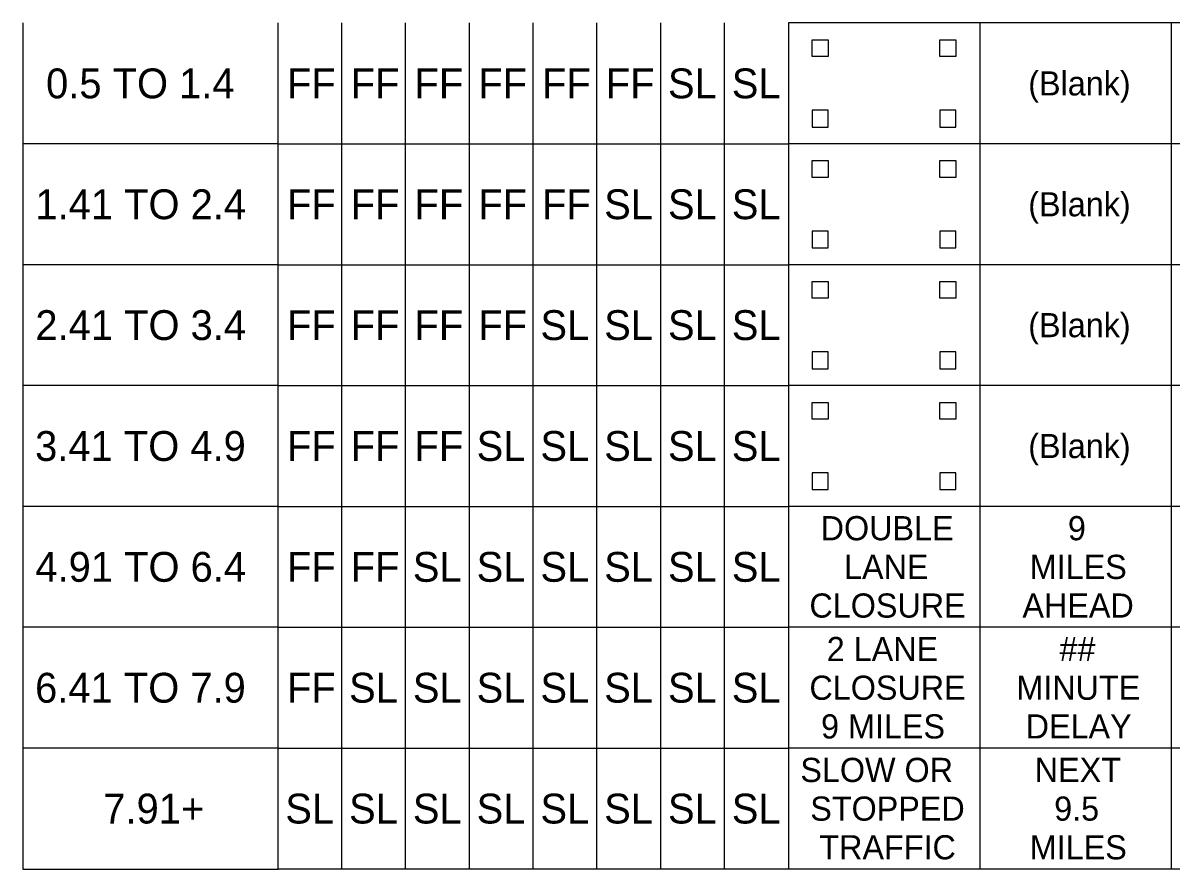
# Model space of a CAD drawing. Extents: x 99999.1 to 100055.7, y 99995 to 100017.5.
# Drawn here: x 100024.329 to 100027.417, y 100001.966 to 100004.241 of the extents above; entities that cross this region are included whole.
import ezdxf

# ---------------------------------------------------------------- set-up
doc = ezdxf.new("R2010")
doc.units = 0
doc.layers.add('TR_WZ_WorkZoneDetails', color=7, linetype='Continuous')
doc.layers.add('TR_WZ_WorkZoneTextCurrent', color=7, linetype='Continuous')

msp = doc.modelspace()

# ---------------------------------------------------------------- linework, layer by layer
at = {"layer": 'TR_WZ_WorkZoneDetails'}
for p, q in [((100024.3292, 100004.2408), (100024.3292, 100003.9158)), ((100025.0153, 100003.9158), (100025.0153, 100004.2408)), ((100025.1868, 100003.9158), (100025.1868, 100004.2408)), ((100025.1868, 100003.9158), (100025.1868, 100004.2408)), ((100025.3583, 100003.9158), (100025.3583, 100004.2408)), ((100025.3583, 100003.9158), (100025.3583, 100004.2408)), ((100025.5299, 100003.9158), (100025.5299, 100004.2408)), ((100025.7014, 100003.9158), (100025.7014, 100004.2408)), ((100025.8729, 100003.9158), (100025.8729, 100004.2408)), ((100026.0444, 100003.9158), (100026.0444, 100004.2408)), ((100026.216, 100003.9158), (100026.216, 100004.2408)), ((100026.3875, 100004.2408), (100026.3875, 100003.9158)), ((100027.4167, 100004.2408), (100026.3875, 100004.2408)), ((100026.9021, 100004.2408), (100026.9021, 100003.9158)), ((100028.4458, 100004.2408), (100027.4167, 100004.2408)), ((100027.4167, 100004.2408), (100027.4167, 100003.9158)), ((100025.0153, 100003.9158), (100024.3292, 100003.9158)), ((100024.3292, 100003.9158), (100024.3292, 100003.5908)), ((100025.0153, 100003.5908), (100025.0153, 100003.9158)), ((100025.0153, 100003.9158), (100025.1868, 100003.9158)), ((100025.1868, 100003.9158), (100025.3583, 100003.9158)), ((100025.1868, 100003.5908), (100025.1868, 100003.9158)), ((100025.1868, 100003.5908), (100025.1868, 100003.9158)), ((100025.3583, 100003.5908), (100025.3583, 100003.9158)), ((100025.3583, 100003.9158), (100025.5299, 100003.9158)), ((100025.3583, 100003.5908), (100025.3583, 100003.9158)), ((100025.5299, 100003.5908), (100025.5299, 100003.9158)), ((100025.5299, 100003.9158), (100025.7014, 100003.9158)), ((100025.7014, 100003.5908), (100025.7014, 100003.9158)), ((100025.7014, 100003.9158), (100025.8729, 100003.9158)), ((100025.8729, 100003.5908), (100025.8729, 100003.9158)), ((100025.8729, 100003.9158), (100026.0444, 100003.9158)), ((100026.0444, 100003.5908), (100026.0444, 100003.9158)), ((100026.0444, 100003.9158), (100026.216, 100003.9158)), ((100026.216, 100003.5908), (100026.216, 100003.9158)), ((100026.216, 100003.9158), (100026.3875, 100003.9158)), ((100026.3875, 100003.9158), (100026.3875, 100003.5908)), ((100027.4167, 100003.9158), (100026.3875, 100003.9158)), ((100026.9021, 100003.9158), (100026.9021, 100003.5908)), ((100028.4458, 100003.9158), (100027.4167, 100003.9158)), ((100027.4167, 100003.9158), (100027.4167, 100003.5908)), ((100025.0153, 100003.5908), (100024.3292, 100003.5908)), ((100024.3292, 100003.5908), (100024.3292, 100003.2658)), ((100025.0153, 100003.2658), (100025.0153, 100003.5908)), ((100025.0153, 100003.5908), (100025.1868, 100003.5908)), ((100025.1868, 100003.5908), (100025.3583, 100003.5908)), ((100025.1868, 100003.2658), (100025.1868, 100003.5908)), ((100025.1868, 100003.2658), (100025.1868, 100003.5908)), ((100025.3583, 100003.2658), (100025.3583, 100003.5908)), ((100025.3583, 100003.5908), (100025.5299, 100003.5908)), ((100025.3583, 100003.2658), (100025.3583, 100003.5908)), ((100025.5299, 100003.2658), (100025.5299, 100003.5908)), ((100025.5299, 100003.5908), (100025.7014, 100003.5908)), ((100025.7014, 100003.2658), (100025.7014, 100003.5908)), ((100025.7014, 100003.5908), (100025.8729, 100003.5908)), ((100025.8729, 100003.2658), (100025.8729, 100003.5908)), ((100025.8729, 100003.5908), (100026.0444, 100003.5908)), ((100026.0444, 100003.2658), (100026.0444, 100003.5908)), ((100026.0444, 100003.5908), (100026.216, 100003.5908)), ((100026.216, 100003.2658), (100026.216, 100003.5908)), ((100026.216, 100003.5908), (100026.3875, 100003.5908)), ((100026.3875, 100003.5908), (100026.3875, 100003.2658)), ((100027.4167, 100003.5908), (100026.3875, 100003.5908)), ((100026.9021, 100003.5908), (100026.9021, 100003.2658)), ((100028.4458, 100003.5908), (100027.4167, 100003.5908)), ((100027.4167, 100003.5908), (100027.4167, 100003.2658)), ((100025.0153, 100003.2658), (100024.3292, 100003.2658)), ((100024.3292, 100003.2658), (100024.3292, 100002.9408)), ((100025.0153, 100002.9408), (100025.0153, 100003.2658)), ((100025.0153, 100003.2658), (100025.1868, 100003.2658)), ((100025.1868, 100003.2658), (100025.3583, 100003.2658)), ((100025.1868, 100002.9408), (100025.1868, 100003.2658)), ((100025.1868, 100002.9408), (100025.1868, 100003.2658)), ((100025.3583, 100002.9408), (100025.3583, 100003.2658)), ((100025.3583, 100003.2658), (100025.5299, 100003.2658)), ((100025.3583, 100002.9408), (100025.3583, 100003.2658)), ((100025.5299, 100002.9408), (100025.5299, 100003.2658)), ((100025.5299, 100003.2658), (100025.7014, 100003.2658)), ((100025.7014, 100002.9408), (100025.7014, 100003.2658)), ((100025.7014, 100003.2658), (100025.8729, 100003.2658)), ((100025.8729, 100002.9408), (100025.8729, 100003.2658)), ((100025.8729, 100003.2658), (100026.0444, 100003.2658)), ((100026.0444, 100002.9408), (100026.0444, 100003.2658)), ((100026.0444, 100003.2658), (100026.216, 100003.2658)), ((100026.216, 100002.9408), (100026.216, 100003.2658)), ((100026.216, 100003.2658), (100026.3875, 100003.2658)), ((100026.3875, 100003.2658), (100026.3875, 100002.9408)), ((100027.4167, 100003.2658), (100026.3875, 100003.2658)), ((100026.9021, 100003.2658), (100026.9021, 100002.9408)), ((100028.4458, 100003.2658), (100027.4167, 100003.2658)), ((100027.4167, 100003.2658), (100027.4167, 100002.9408)), ((100025.0153, 100002.9408), (100024.3292, 100002.9408)), ((100024.3292, 100002.9408), (100024.3292, 100002.6158)), ((100025.0153, 100002.6158), (100025.0153, 100002.9408)), ((100025.0153, 100002.9408), (100025.1868, 100002.9408)), ((100025.1868, 100002.9408), (100025.3583, 100002.9408)), ((100025.1868, 100002.6158), (100025.1868, 100002.9408)), ((100025.1868, 100002.6158), (100025.1868, 100002.9408)), ((100025.3583, 100002.6158), (100025.3583, 100002.9408)), ((100025.3583, 100002.9408), (100025.5299, 100002.9408)), ((100025.3583, 100002.6158), (100025.3583, 100002.9408)), ((100025.5299, 100002.6158), (100025.5299, 100002.9408)), ((100025.5299, 100002.9408), (100025.7014, 100002.9408)), ((100025.7014, 100002.6158), (100025.7014, 100002.9408)), ((100025.7014, 100002.9408), (100025.8729, 100002.9408)), ((100025.8729, 100002.6158), (100025.8729, 100002.9408)), ((100025.8729, 100002.9408), (100026.0444, 100002.9408)), ((100026.0444, 100002.6158), (100026.0444, 100002.9408)), ((100026.0444, 100002.9408), (100026.216, 100002.9408)), ((100026.216, 100002.6158), (100026.216, 100002.9408)), ((100026.216, 100002.9408), (100026.3875, 100002.9408)), ((100026.3875, 100002.9408), (100026.3875, 100002.6158)), ((100027.4167, 100002.9408), (100026.3875, 100002.9408)), ((100026.9021, 100002.9408), (100026.9021, 100002.6158)), ((100028.4458, 100002.9408), (100027.4167, 100002.9408)), ((100027.4167, 100002.9408), (100027.4167, 100002.6158)), ((100025.0153, 100002.6158), (100024.3292, 100002.6158)), ((100025.0153, 100002.6158), (100024.3292, 100002.6158)), ((100024.3292, 100002.6158), (100024.3292, 100002.2908)), ((100025.0153, 100002.6158), (100025.1868, 100002.6158)), ((100025.0153, 100002.2908), (100025.0153, 100002.6158)), ((100025.0153, 100002.6158), (100025.1868, 100002.6158)), ((100025.1868, 100002.6158), (100025.3583, 100002.6158)), ((100025.1868, 100002.6158), (100025.3583, 100002.6158)), ((100025.1868, 100002.2908), (100025.1868, 100002.6158)), ((100025.1868, 100002.2908), (100025.1868, 100002.6158)), ((100025.3583, 100002.6158), (100025.5299, 100002.6158)), ((100025.3583, 100002.2908), (100025.3583, 100002.6158)), ((100025.3583, 100002.6158), (100025.5299, 100002.6158)), ((100025.3583, 100002.2908), (100025.3583, 100002.6158)), ((100025.5299, 100002.6158), (100025.7014, 100002.6158)), ((100025.5299, 100002.2908), (100025.5299, 100002.6158)), ((100025.5299, 100002.6158), (100025.7014, 100002.6158)), ((100025.7014, 100002.6158), (100025.8729, 100002.6158)), ((100025.7014, 100002.2908), (100025.7014, 100002.6158)), ((100025.7014, 100002.6158), (100025.8729, 100002.6158)), ((100025.8729, 100002.6158), (100026.0444, 100002.6158)), ((100025.8729, 100002.2908), (100025.8729, 100002.6158)), ((100025.8729, 100002.6158), (100026.0444, 100002.6158)), ((100026.0444, 100002.6158), (100026.216, 100002.6158)), ((100026.0444, 100002.2908), (100026.0444, 100002.6158)), ((100026.0444, 100002.6158), (100026.216, 100002.6158)), ((100026.216, 100002.6158), (100026.3875, 100002.6158)), ((100026.216, 100002.2908), (100026.216, 100002.6158)), ((100026.216, 100002.6158), (100026.3875, 100002.6158)), ((100027.4167, 100002.6158), (100026.3875, 100002.6158)), ((100026.3875, 100002.6158), (100026.3875, 100002.2908)), ((100027.4167, 100002.6158), (100026.3875, 100002.6158)), ((100026.9021, 100002.6158), (100026.9021, 100002.2908)), ((100028.4458, 100002.6158), (100027.4167, 100002.6158)), ((100028.4458, 100002.6158), (100027.4167, 100002.6158)), ((100027.4167, 100002.6158), (100027.4167, 100002.2908)), ((100024.3292, 100002.2908), (100024.3292, 100001.9658)), ((100025.0153, 100002.2908), (100024.3292, 100002.2908)), ((100025.0153, 100001.9658), (100025.0153, 100002.2908)), ((100025.0153, 100002.2908), (100025.1868, 100002.2908)), ((100025.1868, 100001.9658), (100025.1868, 100002.2908)), ((100025.1868, 100001.9658), (100025.1868, 100002.2908)), ((100025.1868, 100002.2908), (100025.3583, 100002.2908)), ((100025.3583, 100001.9658), (100025.3583, 100002.2908)), ((100025.3583, 100001.9658), (100025.3583, 100002.2908)), ((100025.3583, 100002.2908), (100025.5299, 100002.2908)), ((100025.5299, 100001.9658), (100025.5299, 100002.2908)), ((100025.5299, 100002.2908), (100025.7014, 100002.2908)), ((100025.7014, 100001.9658), (100025.7014, 100002.2908)), ((100025.7014, 100002.2908), (100025.8729, 100002.2908)), ((100025.8729, 100001.9658), (100025.8729, 100002.2908)), ((100025.8729, 100002.2908), (100026.0444, 100002.2908)), ((100026.0444, 100001.9658), (100026.0444, 100002.2908)), ((100026.0444, 100002.2908), (100026.216, 100002.2908)), ((100026.216, 100001.9658), (100026.216, 100002.2908)), ((100026.216, 100002.2908), (100026.3875, 100002.2908)), ((100026.3875, 100002.2908), (100026.3875, 100001.9658)), ((100027.4167, 100002.2908), (100026.3875, 100002.2908)), ((100026.9021, 100002.2908), (100026.9021, 100001.9658)), ((100027.4167, 100002.2908), (100027.4167, 100001.9658)), ((100028.4458, 100002.2908), (100027.4167, 100002.2908)), ((100024.3292, 100001.9658), (100025.0153, 100001.9658)), ((100025.1868, 100001.9658), (100025.0153, 100001.9658)), ((100025.3583, 100001.9658), (100025.1868, 100001.9658)), ((100025.5299, 100001.9658), (100025.3583, 100001.9658)), ((100025.7014, 100001.9658), (100025.5299, 100001.9658)), ((100025.8729, 100001.9658), (100025.7014, 100001.9658)), ((100026.0444, 100001.9658), (100025.8729, 100001.9658)), ((100026.216, 100001.9658), (100026.0444, 100001.9658)), ((100026.3875, 100001.9658), (100026.216, 100001.9658)), ((100027.4167, 100001.9658), (100026.3875, 100001.9658)), ((100028.4458, 100001.9658), (100027.4167, 100001.9658))]:
    msp.add_line(p, q, dxfattribs=at)
at = {"layer": 'TR_WZ_WorkZoneTextCurrent'}
for points in [[(100026.4518, 100004.1956), (100026.4947, 100004.1956), (100026.4947, 100004.1505), (100026.4518, 100004.1505)], [(100026.7949, 100004.1956), (100026.8378, 100004.1956), (100026.8378, 100004.1505), (100026.7949, 100004.1505)], [(100026.4518, 100003.9609), (100026.4947, 100003.9609), (100026.4947, 100004.0061), (100026.4518, 100004.0061)], [(100026.7949, 100003.9609), (100026.8378, 100003.9609), (100026.8378, 100004.0061), (100026.7949, 100004.0061)], [(100026.4518, 100003.8706), (100026.4947, 100003.8706), (100026.4947, 100003.8255), (100026.4518, 100003.8255)], [(100026.7949, 100003.8706), (100026.8378, 100003.8706), (100026.8378, 100003.8255), (100026.7949, 100003.8255)], [(100026.4518, 100003.6359), (100026.4947, 100003.6359), (100026.4947, 100003.6811), (100026.4518, 100003.6811)], [(100026.7949, 100003.6359), (100026.8378, 100003.6359), (100026.8378, 100003.6811), (100026.7949, 100003.6811)], [(100026.4518, 100003.5456), (100026.4947, 100003.5456), (100026.4947, 100003.5005), (100026.4518, 100003.5005)], [(100026.7949, 100003.5456), (100026.8378, 100003.5456), (100026.8378, 100003.5005), (100026.7949, 100003.5005)], [(100026.4518, 100003.3109), (100026.4947, 100003.3109), (100026.4947, 100003.3561), (100026.4518, 100003.3561)], [(100026.7949, 100003.3109), (100026.8378, 100003.3109), (100026.8378, 100003.3561), (100026.7949, 100003.3561)], [(100026.4518, 100003.2206), (100026.4947, 100003.2206), (100026.4947, 100003.1755), (100026.4518, 100003.1755)], [(100026.7949, 100003.2206), (100026.8378, 100003.2206), (100026.8378, 100003.1755), (100026.7949, 100003.1755)], [(100026.4518, 100002.9859), (100026.4947, 100002.9859), (100026.4947, 100003.0311), (100026.4518, 100003.0311)], [(100026.7949, 100002.9859), (100026.8378, 100002.9859), (100026.8378, 100003.0311), (100026.7949, 100003.0311)]]:
    msp.add_lwpolyline(points, close=True, dxfattribs=at)

# ---------------------------------------------------------------- texts
for s, height, p in [('0.5 TO 1.4', 0.08025, (100024.3913, 100004.0382)), ('FF', 0.08025, (100025.039, 100004.0382)), ('FF', 0.08025, (100025.2105, 100004.0382)), ('FF', 0.08025, (100025.3821, 100004.0382)), ('FF', 0.08025, (100025.5536, 100004.0382)), ('FF', 0.08025, (100025.7251, 100004.0382)), ('FF', 0.08025, (100025.8966, 100004.0382)), ('SL', 0.08025, (100026.0638, 100004.0382)), ('SL', 0.08025, (100026.2354, 100004.0382)), ('(Blank)', 0.065, (100027.0327, 100004.0458)), ('1.41 TO 2.4', 0.080247, (100024.3625, 100003.7132)), ('FF', 0.08025, (100025.039, 100003.7132)), ('FF', 0.08025, (100025.2105, 100003.7132)), ('FF', 0.08025, (100025.3821, 100003.7132)), ('FF', 0.08025, (100025.5536, 100003.7132)), ('FF', 0.08025, (100025.7251, 100003.7132)), ('SL', 0.08025, (100025.8923, 100003.7132)), ('SL', 0.08025, (100026.0638, 100003.7132)), ('SL', 0.08025, (100026.2354, 100003.7132)), ('(Blank)', 0.065, (100027.0327, 100003.7208)), ('2.41 TO 3.4', 0.080247, (100024.3625, 100003.3882)), ('FF', 0.08025, (100025.039, 100003.3882)), ('FF', 0.08025, (100025.2105, 100003.3882)), ('FF', 0.08025, (100025.3821, 100003.3882)), ('FF', 0.08025, (100025.5536, 100003.3882)), ('SL', 0.08025, (100025.7208, 100003.3882)), ('SL', 0.08025, (100025.8923, 100003.3882)), ('SL', 0.08025, (100026.0638, 100003.3882)), ('SL', 0.08025, (100026.2354, 100003.3882)), ('(Blank)', 0.065, (100027.0327, 100003.3958)), ('3.41 TO 4.9', 0.080247, (100024.3618, 100003.0632)), ('FF', 0.08025, (100025.039, 100003.0632)), ('FF', 0.08025, (100025.2105, 100003.0632)), ('FF', 0.08025, (100025.3821, 100003.0632)), ('SL', 0.08025, (100025.5492, 100003.0632)), ('SL', 0.08025, (100025.7208, 100003.0632)), ('SL', 0.08025, (100025.8923, 100003.0632)), ('SL', 0.08025, (100026.0638, 100003.0632)), ('SL', 0.08025, (100026.2354, 100003.0632)), ('(Blank)', 0.065, (100027.0327, 100003.0708)), ('DOUBLE', 0.065, (100026.4744, 100002.8498)), ('9', 0.065, (100027.1393, 100002.8498)), ('4.91 TO 6.4', 0.080247, (100024.3625, 100002.7382)), ('FF', 0.08025, (100025.039, 100002.7382)), ('FF', 0.08025, (100025.2105, 100002.7382)), ('SL', 0.08025, (100025.3777, 100002.7382)), ('SL', 0.08025, (100025.5492, 100002.7382)), ('SL', 0.08025, (100025.7208, 100002.7382)), ('SL', 0.08025, (100025.8923, 100002.7382)), ('SL', 0.08025, (100026.0638, 100002.7382)), ('SL', 0.08025, (100026.2354, 100002.7382)), ('LANE', 0.065, (100026.5373, 100002.7458)), ('MILES', 0.065, (100027.0368, 100002.7458)), ('CLOSURE', 0.065, (100026.4442, 100002.6418)), ('AHEAD', 0.065, (100027.017, 100002.6418)), ('2 LANE', 0.065, (100026.4907, 100002.5248)), ('##', 0.065, (100027.1166, 100002.5248)), ('6.41 TO 7.9', 0.080247, (100024.3618, 100002.4132)), ('FF', 0.08025, (100025.039, 100002.4132)), ('SL', 0.08025, (100025.2062, 100002.4132)), ('SL', 0.08025, (100025.3777, 100002.4132)), ('SL', 0.08025, (100025.5492, 100002.4132)), ('SL', 0.08025, (100025.7208, 100002.4132)), ('SL', 0.08025, (100025.8923, 100002.4132)), ('SL', 0.08025, (100026.0638, 100002.4132)), ('SL', 0.08025, (100026.2354, 100002.4132)), ('CLOSURE', 0.065, (100026.4442, 100002.4208)), ('MINUTE', 0.065, (100027.0007, 100002.4208)), ('9 MILES', 0.065, (100026.4755, 100002.3168)), ('DELAY', 0.065, (100027.0257, 100002.3168)), ('SLOW OR', 0.065, (100026.4198, 100002.1998)), ('NEXT', 0.065, (100027.0502, 100002.1998)), ('7.91+', 0.08025, (100024.5452, 100002.0882)), ('SL', 0.08025, (100025.0347, 100002.0882)), ('SL', 0.08025, (100025.2062, 100002.0882)), ('SL', 0.08025, (100025.3777, 100002.0882)), ('SL', 0.08025, (100025.5492, 100002.0882)), ('SL', 0.08025, (100025.7208, 100002.0882)), ('SL', 0.08025, (100025.8923, 100002.0882)), ('SL', 0.08025, (100026.0638, 100002.0882)), ('SL', 0.08025, (100026.2354, 100002.0882)), ('STOPPED', 0.065, (100026.4465, 100002.0958)), ('9.5', 0.065, (100027.1024, 100002.0958)), ('TRAFFIC', 0.065, (100026.471, 100001.9918)), ('MILES', 0.065, (100027.0368, 100001.9918))]:
    msp.add_text(s, height=height, rotation=360, dxfattribs=at).set_placement(p)

doc.saveas('drawing.dxf')
